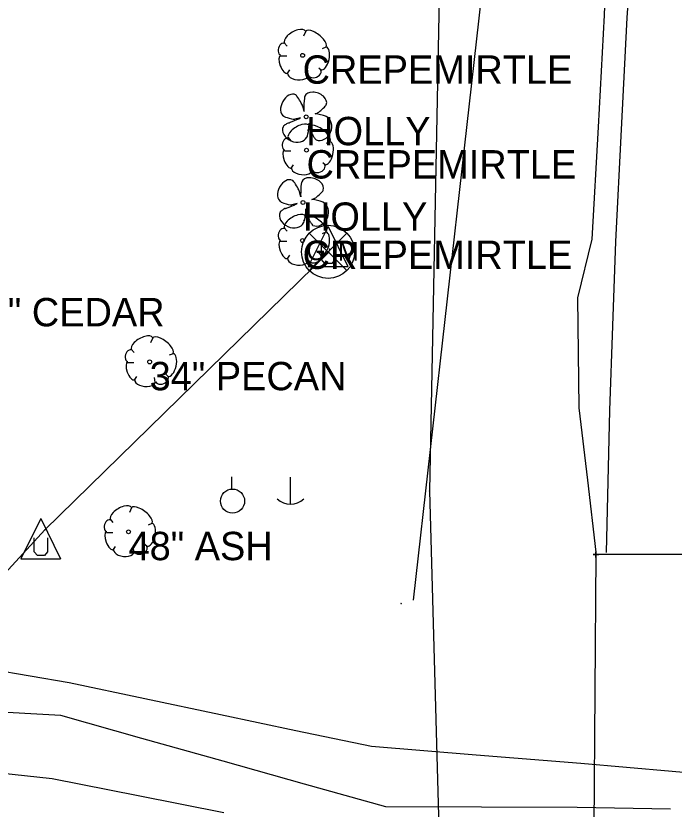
# Model space of a CAD drawing. Extents: x 1930288 to 1941089, y 588389 to 611475.
# Drawn here: x 1930758.4 to 1930874.5, y 598182.1 to 598322 of the extents above; entities that cross this region are included whole.
import ezdxf

# ---------------------------------------------------------------- set-up
doc = ezdxf.new("R2010")
doc.units = 0
for name, color, linetype in [('S_BRIDGE', 7, 'Continuous'), ('S_DITCHLINE', 7, 'Continuous'), ('S_EDGE_PAVEMENT', 7, 'Continuous'), ('S_GAS_UTILITIES', 7, 'Continuous'), ('S_SHOULDER', 7, 'Continuous'), ('S_STORM_SEWER', 7, 'Continuous'), ('S_STR_PT_SYM', 7, 'Continuous'), ('S_STREAM', 7, 'Continuous'), ('S_TREE', 7, 'Continuous'), ('S_TREE_ANNOT', 7, 'Continuous'), ('S_UNDERGROUND_CABLE', 7, 'Continuous'), ('S_UTILITY_POLE', 7, 'Continuous'), ('S_UTL_PT_SYM', 7, 'Continuous'), ('S_WATER_UTILITIES', 7, 'Continuous')]:
    doc.layers.add(name, color=color, linetype=linetype)

msp = doc.modelspace()

# ---------------------------------------------------------------- linework, layer by layer
at = {"layer": 'S_BRIDGE'}
for p, q in [((1930860.72, 598227), (1930860.05, 598137.01)), ((1930888.36, 598226.99), (1930860.72, 598227))]:
    msp.add_line(p, q, dxfattribs=at)
at = {"layer": 'S_DITCHLINE'}
msp.add_lwpolyline([(1930873.87, 598182.1), (1930857.41, 598182.4), (1930840.53, 598182.46), (1930823.65, 598182.52), (1930809.32, 598186.54), (1930794.99, 598190.57), (1930780.66, 598194.59), (1930766.34, 598198.62), (1930752.63, 598199.42), (1930738.92, 598200.23), (1930725.22, 598201.03), (1930711.51, 598201.83), (1930697.9, 598201.47), (1930684.3, 598201.1), (1930670.69, 598200.73), (1930657.08, 598200.36), (1930638.19, 598198.83)], dxfattribs=at)
at = {"layer": 'S_EDGE_PAVEMENT'}
msp.add_lwpolyline([(1930877.33, 598456.1), (1930875.68, 598439.46), (1930874.03, 598422.82), (1930872.39, 598406.18), (1930870.73, 598384.64), (1930869.07, 598363.1), (1930867.63, 598342.37), (1930866.18, 598321.65), (1930865.17, 598301.92), (1930864.16, 598282.2), (1930863.63, 598267.31), (1930863.11, 598252.42), (1930862.8, 598239.89), (1930862.49, 598227.37)], dxfattribs=at)
at = {"layer": 'S_GAS_UTILITIES'}
for p, q in [((1930810.17, 598277.06), (1930816.79, 598283.68)), ((1930810.17, 598283.68), (1930816.79, 598277.06)), ((1930813.6, 598280.32), (1930763.56, 598231.34)), ((1930763.56, 598231.34), (1930683.07, 598144.05))]:
    msp.add_line(p, q, dxfattribs=at)
msp.add_circle((1930813.48, 598280.37), 4.68, dxfattribs=at)
at = {"layer": 'S_SHOULDER'}
msp.add_lwpolyline([(1930871.29, 598453.49), (1930868.81, 598433.59), (1930867.64, 598420.35), (1930866.47, 598407.12), (1930865.09, 598385.12), (1930863.71, 598363.13), (1930862.94, 598342.62), (1930862.17, 598322.12), (1930861.08, 598302.35), (1930859.98, 598282.59), (1930857.48, 598272.25), (1930857.72, 598252.88), (1930859.2, 598240.14), (1930860.69, 598227.4)], dxfattribs=at)
at = {"layer": 'S_STORM_SEWER'}
msp.add_line((1930841.9, 598337.67), (1930828.48, 598218.96), dxfattribs=at)
at = {"layer": 'S_STR_PT_SYM'}
msp.add_lwpolyline([(1930860.72, 598227), (1930860.72, 598227.5), (1930860.72, 598227), (1930860.22, 598227), (1930860.72, 598227), (1930860.72, 598226.5), (1930860.72, 598227), (1930861.22, 598227)], dxfattribs=at)
at = {"layer": 'S_STREAM'}
for points in [[(1930906.83, 598185.8), (1930890.27, 598187.32), (1930874.15, 598188.74), (1930858.02, 598190.16), (1930839.57, 598191.65), (1930821.12, 598193.14), (1930807.8, 598195.95), (1930794.49, 598198.75), (1930781.17, 598201.56), (1930767.85, 598204.36), (1930754.04, 598206.75), (1930740.24, 598209.13), (1930726.43, 598211.51), (1930712.62, 598213.9), (1930698.26, 598212.92), (1930683.89, 598211.94), (1930669.53, 598210.96), (1930655.17, 598209.99), (1930636.67, 598208.34)], [(1930795.11, 598181.46), (1930779.97, 598184.46), (1930764.83, 598187.45), (1930751.2, 598188.94), (1930737.57, 598190.42), (1930723.94, 598191.9), (1930710.31, 598193.39), (1930697.04, 598191.91), (1930683.76, 598190.43), (1930670.49, 598188.95), (1930657.21, 598187.47), (1930638.3, 598187.25)]]:
    msp.add_lwpolyline(points, dxfattribs=at)
at = {"layer": 'S_TREE'}
for p, q in [((1930809.55, 598319.26), (1930809.16, 598318.4)), ((1930805.75, 598317.24), (1930806.25, 598316.66)), ((1930813.11, 598316.47), (1930812.45, 598316.19)), ((1930805.09, 598314.92), (1930806.21, 598314.92)), ((1930806.25, 598311.74), (1930806.72, 598312.44)), ((1930809.93, 598311.47), (1930809.86, 598312.24)), ((1930812.34, 598312.36), (1930811.87, 598312.78)), ((1930809.25, 598305.15), (1930809.01, 598306.04)), ((1930811.2, 598304.69), (1930811.58, 598304.85)), ((1930808.6, 598303.98), (1930807.63, 598303.77)), ((1930810.24, 598302.55), (1930809.85, 598301.69)), ((1930810.13, 598303.05), (1930810.21, 598302.61)), ((1930806.44, 598300.53), (1930806.94, 598299.95)), ((1930813.8, 598299.76), (1930813.14, 598299.49)), ((1930805.78, 598298.21), (1930806.9, 598298.21)), ((1930806.94, 598295.03), (1930807.41, 598295.73)), ((1930810.62, 598294.76), (1930810.55, 598295.53)), ((1930813.03, 598295.65), (1930812.56, 598296.08)), ((1930808.69, 598290.06), (1930808.45, 598290.95)), ((1930810.64, 598289.6), (1930811.02, 598289.76)), ((1930808.05, 598288.9), (1930807.07, 598288.68)), ((1930809.58, 598287.96), (1930809.66, 598287.53)), ((1930809.54, 598286.61), (1930809.15, 598285.76)), ((1930805.74, 598284.6), (1930806.25, 598284.01)), ((1930813.11, 598283.82), (1930812.45, 598283.55)), ((1930805.08, 598282.27), (1930806.21, 598282.27)), ((1930806.25, 598279.09), (1930806.71, 598279.79)), ((1930809.93, 598278.82), (1930809.85, 598279.6)), ((1930812.33, 598279.71), (1930811.87, 598280.14)), ((1930782.58, 598265.21), (1930782.19, 598264.36)), ((1930778.78, 598263.2), (1930779.29, 598262.62)), ((1930786.15, 598262.42), (1930785.49, 598262.15)), ((1930778.13, 598260.87), (1930779.25, 598260.87)), ((1930785.37, 598258.32), (1930784.91, 598258.74)), ((1930779.29, 598257.7), (1930779.75, 598258.39)), ((1930782.97, 598257.42), (1930782.89, 598258.2)), ((1930778.85, 598235.25), (1930778.47, 598234.4)), ((1930775.06, 598233.24), (1930775.56, 598232.66)), ((1930782.42, 598232.46), (1930781.76, 598232.19)), ((1930774.4, 598230.91), (1930775.52, 598230.91)), ((1930775.56, 598227.73), (1930776.03, 598228.43)), ((1930779.24, 598227.46), (1930779.16, 598228.24)), ((1930781.64, 598228.35), (1930781.18, 598228.78))]:
    msp.add_line(p, q, dxfattribs=at)
for centre in [(1930808.99, 598315.01), (1930809.62, 598304.17), (1930809.68, 598298.3), (1930809.06, 598289.08), (1930808.98, 598282.36), (1930782.02, 598260.97), (1930778.3, 598231.01)]:
    msp.add_circle(centre, 0.341, dxfattribs=at)
for centre, major_axis, ratio, start_param, end_param in [((1930807.65, 598318.21), (1.86, 1.08), 0.471018, 0, 3.141593), ((1930811.31, 598317.89), (-1.81, 1.36), 0.405113, 3.141593, 6.283186), ((1930805.42, 598316.1), (0.31, 1.03), 0.646762, 0, 3.141593), ((1930812.66, 598314.48), (0.46, 2.04), 0.482994, 3.141593, 6.283185), ((1930805.72, 598313.45), (-0.61, 1.6), 0.420543, 6.283185, 9.424777), ((1930808.18, 598311.67), (-1.83, 0.19), 0.529943, 0, 3.141593), ((1930811.14, 598311.96), (1.09, 0.46), 0.711534, 3.141592, 6.283185), ((1930806.73, 598306.19), (-1.03, -1.88), 0.662338, 3.141593, 6.283185), ((1930808.38, 598307.06), (0.62, -1.01), 0.083512, 0, 3.141593), ((1930809.32, 598306.47), (-0.07, -1.33), 0.068203, 3.141593, 6.283185), ((1930811.28, 598307.06), (1.89, -0.74), 0.673998, 0, 3.141593), ((1930812.37, 598305.58), (-0.798, -0.73), 0.092159, 0, 3.141593), ((1930812.16, 598304.46), (0.96, -0.23), 0.056001, 0, 3.141593), ((1930806.66, 598304.03), (0.964, -0.267), 0.113563, 3.141593, 6.283185), ((1930807.56, 598303.54), (1.04, 0.44), 0.002756, 3.141593, 6.283185), ((1930812.24, 598302.18), (0.88, 2.05), 0.81717, 3.141593, 6.283185), ((1930807.64, 598301.51), (2.07, -0.93), 0.760068, 3.141593, 6.283185), ((1930806.05, 598302.77), (0.477, 0.328), 0.136309, 0, 3.141593), ((1930808.34, 598301.5), (1.86, 1.08), 0.471018, 0, 3.141593), ((1930809.9, 598301.89), (0.19, 1.31), 0.114148, 3.141593, 5.822668), ((1930812, 598301.18), (-1.81, 1.36), 0.405113, 3.141593, 6.283186), ((1930810.47, 598301.84), (0.254, -0.771), 0.051603, 3.141593, 6.283185), ((1930806.11, 598299.39), (0.31, 1.03), 0.646762, 0, 3.141593), ((1930811.04, 598300.61), (-0.321, 0.467), 0.094289, 0, 3.141593), ((1930813.35, 598297.77), (0.46, 2.04), 0.482994, 3.141593, 6.283185), ((1930806.41, 598296.74), (-0.61, 1.6), 0.420543, 6.283185, 9.424777), ((1930808.87, 598294.96), (-1.83, 0.19), 0.529943, 0, 3.141593), ((1930811.83, 598295.25), (1.09, 0.46), 0.711534, 3.141592, 6.283185), ((1930810.72, 598291.97), (1.89, -0.74), 0.673998, 0, 3.141593), ((1930806.17, 598291.1), (-1.03, -1.88), 0.662338, 3.141593, 6.283185), ((1930807.83, 598291.97), (0.62, -1.01), 0.083512, 0, 3.141593), ((1930808.76, 598291.38), (-0.07, -1.33), 0.068203, 3.141593, 6.283185), ((1930811.82, 598290.49), (-0.798, -0.73), 0.092159, 0, 3.141593), ((1930811.6, 598289.37), (0.96, -0.23), 0.056001, 0, 3.141593), ((1930805.49, 598287.68), (0.477, 0.328), 0.136309, 0, 3.141593), ((1930806.11, 598288.95), (0.964, -0.267), 0.113563, 3.141593, 6.283185), ((1930807.01, 598288.45), (1.04, 0.44), 0.002756, 3.141593, 6.283185), ((1930809.34, 598286.8), (0.19, 1.31), 0.114148, 3.141593, 5.822668), ((1930811.68, 598287.09), (0.88, 2.05), 0.81717, 3.141593, 6.283185), ((1930807.08, 598286.42), (2.07, -0.93), 0.760068, 3.141593, 6.283185), ((1930807.65, 598285.57), (1.86, 1.08), 0.471018, 0, 3.141593), ((1930811.3, 598285.24), (-1.81, 1.36), 0.405113, 3.141593, 6.283186), ((1930809.91, 598286.75), (0.254, -0.771), 0.051603, 3.141593, 6.283185), ((1930810.49, 598285.52), (-0.321, 0.467), 0.094289, 0, 3.141593), ((1930805.41, 598283.45), (0.31, 1.03), 0.646762, 0, 3.141593), ((1930812.66, 598281.84), (0.46, 2.04), 0.482994, 3.141593, 6.283185), ((1930805.72, 598280.8), (-0.61, 1.6), 0.420543, 6.283185, 9.424777), ((1930811.14, 598279.31), (1.09, 0.46), 0.711534, 3.141592, 6.283185), ((1930808.18, 598279.02), (-1.83, 0.19), 0.529943, 0, 3.141593), ((1930780.69, 598264.17), (1.86, 1.08), 0.471018, 0, 3.141593), ((1930784.34, 598263.85), (-1.81, 1.36), 0.405113, 3.141593, 6.283186), ((1930778.45, 598262.06), (0.31, 1.03), 0.646762, 0, 3.141593), ((1930785.7, 598260.44), (0.46, 2.04), 0.482994, 3.141593, 6.283185), ((1930778.76, 598259.41), (-0.61, 1.6), 0.420543, 6.283185, 9.424777), ((1930781.22, 598257.62), (-1.83, 0.19), 0.529943, 0, 3.141593), ((1930784.18, 598257.92), (1.09, 0.46), 0.711534, 3.141592, 6.283185), ((1930776.96, 598234.21), (1.86, 1.08), 0.471018, 0, 3.141593), ((1930780.62, 598233.89), (-1.81, 1.36), 0.405113, 3.141593, 6.283186), ((1930774.73, 598232.09), (0.31, 1.03), 0.646762, 0, 3.141593), ((1930781.97, 598230.48), (0.46, 2.04), 0.482994, 3.141593, 6.283185), ((1930775.03, 598229.44), (-0.61, 1.6), 0.420543, 6.283185, 9.424777), ((1930777.49, 598227.66), (-1.83, 0.19), 0.529943, 0, 3.141593), ((1930780.45, 598227.96), (1.09, 0.46), 0.711534, 3.141592, 6.283185)]:
    msp.add_ellipse(centre, major_axis=major_axis, ratio=ratio, start_param=start_param, end_param=end_param, dxfattribs=at)
at = {"layer": 'S_UNDERGROUND_CABLE'}
for p, q in [((1930813.51, 598284.85), (1930809.98, 598277.76)), ((1930813.51, 598284.85), (1930816.99, 598277.76)), ((1930812.31, 598279), (1930812.31, 598281.44)), ((1930814.67, 598281.44), (1930814.67, 598279)), ((1930812.93, 598278.34), (1930812.31, 598279)), ((1930814.13, 598278.34), (1930812.93, 598278.34)), ((1930814.67, 598279), (1930814.13, 598278.34)), ((1930809.98, 598277.76), (1930816.99, 598277.76)), ((1930762.84, 598233.35), (1930759.31, 598226.26)), ((1930762.84, 598233.35), (1930766.33, 598226.26)), ((1930761.64, 598227.5), (1930761.64, 598229.94)), ((1930764, 598229.94), (1930764, 598227.5)), ((1930762.26, 598226.84), (1930761.64, 598227.5)), ((1930763.46, 598226.84), (1930762.26, 598226.84)), ((1930764, 598227.5), (1930763.46, 598226.84)), ((1930759.31, 598226.26), (1930766.33, 598226.26))]:
    msp.add_line(p, q, dxfattribs=at)
at = {"layer": 'S_UTILITY_POLE'}
for p, q in [((1930796.51, 598238.57), (1930796.51, 598240.68)), ((1930806.8, 598240.62), (1930806.8, 598235.9))]:
    msp.add_line(p, q, dxfattribs=at)
msp.add_circle((1930796.63, 598236.43), 2.13, dxfattribs=at)
msp.add_arc((1930806.86, 598239.32), 3.41, 226.3972, 313.6028, dxfattribs=at)
at = {"layer": 'S_UTL_PT_SYM'}
for points in [[(1930821.24, 598295.79), (1930821.24, 598295.84), (1930821.24, 598295.79), (1930821.19, 598295.79), (1930821.24, 598295.79), (1930821.24, 598295.74), (1930821.24, 598295.79), (1930821.29, 598295.79)], [(1930813.74, 598280.84), (1930813.74, 598280.89), (1930813.74, 598280.84), (1930813.69, 598280.84), (1930813.74, 598280.84), (1930813.74, 598280.79), (1930813.74, 598280.84), (1930813.79, 598280.84)], [(1930813.6, 598280.32), (1930813.6, 598280.37), (1930813.6, 598280.32), (1930813.55, 598280.32), (1930813.6, 598280.32), (1930813.6, 598280.27), (1930813.6, 598280.32), (1930813.65, 598280.32)], [(1930831.37, 598238.21), (1930831.37, 598238.26), (1930831.37, 598238.21), (1930831.32, 598238.21), (1930831.37, 598238.21), (1930831.37, 598238.16), (1930831.37, 598238.21), (1930831.42, 598238.21)], [(1930763.56, 598231.34), (1930763.56, 598231.39), (1930763.56, 598231.34), (1930763.51, 598231.34), (1930763.56, 598231.34), (1930763.56, 598231.29), (1930763.56, 598231.34), (1930763.61, 598231.34)], [(1930826.35, 598218.4), (1930826.35, 598218.45), (1930826.35, 598218.4), (1930826.3, 598218.4), (1930826.35, 598218.4), (1930826.35, 598218.35), (1930826.35, 598218.4), (1930826.4, 598218.4)]]:
    msp.add_lwpolyline(points, dxfattribs=at)
at = {"layer": 'S_WATER_UTILITIES'}
for p, q in [((1930835.68, 598459.98), (1930831.37, 598238.21)), ((1930831.37, 598238.21), (1930837.98, 598000.7))]:
    msp.add_line(p, q, dxfattribs=at)

# ---------------------------------------------------------------- texts
at = {"layer": 'S_GAS_UTILITIES'}
for s, p in [('G', (1930809.66, 598278.91)), ('M', (1930815.22, 598278.8))]:
    msp.add_text(s, height=3.3, rotation=360, dxfattribs=at).set_placement(p)
at = {"layer": 'S_TREE_ANNOT'}
for s, p in [('CREPEMIRTLE', (1930808.99, 598310.01)), ('HOLLY', (1930809.62, 598299.17)), ('CREPEMIRTLE', (1930809.68, 598293.3)), ('HOLLY', (1930809.06, 598284.08)), ('CREPEMIRTLE', (1930808.98, 598277.36)), ('28" CEDAR', (1930749.58, 598267.24)), ('34" PECAN', (1930782.02, 598255.97)), ('48" ASH', (1930778.3, 598226.01))]:
    msp.add_text(s, height=5, dxfattribs=at).set_placement(p)

doc.saveas('drawing.dxf')
